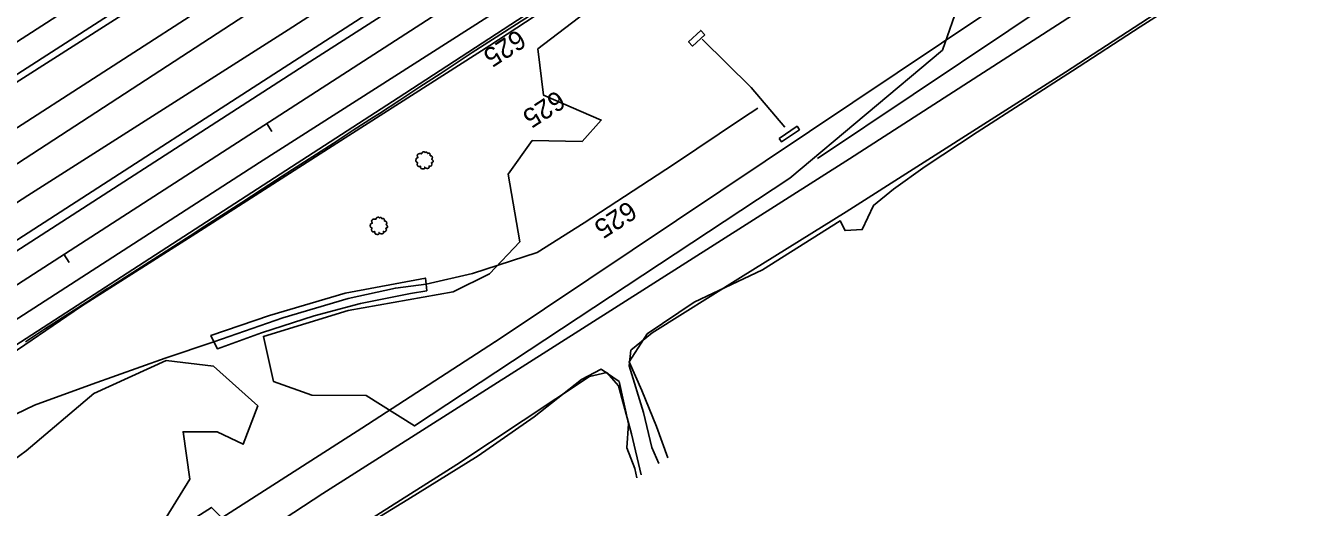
# Model space of a CAD drawing. Extents: x 1901471 to 1963503, y 756461 to 799997.
# Drawn here: x 1919489 to 1920021, y 766626 to 766826 of the extents above; entities that cross this region are included whole.
import ezdxf

# ---------------------------------------------------------------- set-up
doc = ezdxf.new("R2010")
doc.units = 0
for name, color, linetype in [('RD_DTM_BkLn1', 7, 'Continuous'), ('RD_EX_Bldg', 7, 'Continuous'), ('RD_EX_DR_ErosCtrl', 7, 'Continuous'), ('RD_EX_Fence_Other', 7, 'Continuous'), ('RD_EX_GuardRail', 7, 'Continuous'), ('RD_EX_H2O', 7, 'Continuous'), ('RD_EX_Road', 7, 'Continuous'), ('RD_EX_VEG', 7, 'Continuous'), ('RD_HC_Cl', 7, 'Continuous'), ('RD_HC_Data_Tic', 7, 'Continuous'), ('RD_HC_TX_Sta50', 7, 'Continuous')]:
    doc.layers.add(name, color=color, linetype=linetype)

# ---------------------------------------------------------------- blocks, each defined once
blk = doc.blocks.new('T2')
at = {"layer": 'RD_EX_VEG'}
for points in [[(0.05233333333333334, 7.213166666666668), (-0.24750000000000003, 7.238166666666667), (-0.5723333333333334, 7.138166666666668), (-0.8222500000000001, 7.038250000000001), (-1.0471666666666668, 6.963250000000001), (-1.2720833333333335, 6.863250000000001), (-1.5719166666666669, 6.688416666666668), (-1.7968333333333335, 6.488416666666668), (-1.9218333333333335, 6.2385833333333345), (-1.9718333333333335, 6.013666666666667), (-2.0217500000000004, 5.738833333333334), (-2.0217500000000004, 5.563833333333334), (-2.146666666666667, 5.538833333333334), (-2.296666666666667, 5.563833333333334), (-2.5465000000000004, 5.638833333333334), (-2.796416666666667, 5.638833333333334), (-3.0463333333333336, 5.638833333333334), (-3.3961666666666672, 5.613833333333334), (-3.7460000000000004, 5.613833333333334), (-4.020833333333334, 5.563833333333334), (-4.345750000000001, 5.513916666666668), (-4.720583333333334, 5.389000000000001), (-5.0704166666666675, 5.264000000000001), (-5.37025, 5.014083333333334), (-5.620166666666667, 4.539333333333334), (-5.745166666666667, 4.189500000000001), (-5.895083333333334, 3.9395833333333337), (-5.745166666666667, 3.489833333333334), (-5.570166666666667, 3.139916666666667), (-5.545250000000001, 2.9400000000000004), (-5.470250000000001, 2.5152500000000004), (-5.37025, 2.2903333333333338), (-5.245333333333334, 2.0903333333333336), (-5.320250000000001, 2.065416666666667), (-5.695166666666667, 2.015416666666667), (-5.995000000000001, 1.9155000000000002), (-6.419833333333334, 1.6905833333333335), (-6.644750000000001, 1.465666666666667), (-6.744750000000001, 1.1407500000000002), (-6.769666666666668, 0.7909166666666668), (-6.869583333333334, 0.5910833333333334), (-6.944583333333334, 0.3161666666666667), (-6.969583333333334, 0.2411666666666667), (-7.019583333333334, -0.08366666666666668), (-6.9195833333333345, -0.5335000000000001), (-6.894583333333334, -0.8833333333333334), (-6.769666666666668, -1.1082500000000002), (-6.619750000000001, -1.2830833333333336), (-6.444833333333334, -1.5330000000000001), (-6.045000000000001, -1.7579166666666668), (-5.7201666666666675, -1.8579166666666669), (-5.520250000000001, -1.8828333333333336), (-5.695166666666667, -2.382666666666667), (-5.745166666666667, -2.7325000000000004), (-5.870083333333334, -3.132333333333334), (-5.870083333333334, -3.2072500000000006), (-5.920000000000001, -3.682083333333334), (-5.770166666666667, -4.007000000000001), (-5.695166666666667, -4.38175), (-5.520250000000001, -4.606666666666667), (-5.245333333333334, -4.906583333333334), (-4.9205000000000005, -5.131416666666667), (-4.420666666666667, -5.256416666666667), (-4.020833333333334, -5.231416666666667), (-3.4460833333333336, -5.056500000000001), (-3.1962500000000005, -4.9815000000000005), (-3.2212500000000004, -5.156416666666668), (-3.1962500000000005, -5.531333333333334), (-3.1962500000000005, -5.956083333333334), (-3.0463333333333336, -6.280916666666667), (-2.946333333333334, -6.555833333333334), (-2.796416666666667, -6.805750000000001), (-2.4715000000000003, -7.030583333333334), (-2.07175, -7.1055833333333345), (-1.6469166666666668, -7.2555000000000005), (-1.1970833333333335, -7.330500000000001), (-0.6973333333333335, -7.355500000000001), (-0.09758333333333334, -7.205583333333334), (0.17725000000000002, -7.080583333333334), (0.27725000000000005, -6.905666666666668), (0.47716666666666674, -6.530833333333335), (0.4271666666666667, -6.3059166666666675), (0.4521666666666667, -5.706166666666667), (0.5520833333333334, -5.881166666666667), (0.7270833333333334, -6.231000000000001), (1.2268333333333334, -6.530833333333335), (1.626666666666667, -6.705750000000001), (2.101416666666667, -6.8557500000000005), (2.4013333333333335, -6.930666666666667), (2.8760833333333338, -6.8557500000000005), (3.2510000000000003, -6.780750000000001), (3.6257500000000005, -6.655750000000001), (3.9256666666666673, -6.380916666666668), (4.100583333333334, -6.106000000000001), (4.1505833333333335, -5.831166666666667), (4.2255, -5.456333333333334), (4.275500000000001, -5.281416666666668)], [(4.275500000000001, -5.281416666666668), (4.200583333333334, -5.106416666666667), (4.1505833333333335, -4.856583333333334), (4.2255, -4.881583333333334), (4.4004166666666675, -4.931583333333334), (4.675333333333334, -5.056500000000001), (4.900250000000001, -5.131416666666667), (5.225083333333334, -5.106416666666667), (5.500000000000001, -5.006500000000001), (5.949750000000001, -4.731583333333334), (6.224666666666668, -4.256833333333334), (6.499500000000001, -3.8570000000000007), (6.5745000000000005, -3.5321666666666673), (6.524500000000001, -3.3072500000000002), (6.499500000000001, -2.8075000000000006), (6.299583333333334, -2.5575833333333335), (6.249583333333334, -2.432666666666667), (6.1496666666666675, -2.0328333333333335), (6.224666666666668, -1.9828333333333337), (6.499500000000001, -1.9328333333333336), (6.874333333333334, -1.8079166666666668), (7.149250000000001, -1.6830000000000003), (7.374166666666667, -1.5080000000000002), (7.449083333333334, -1.2830833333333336), (7.424166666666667, -0.8833333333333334), (7.4740833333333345, -0.48350000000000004), (7.399166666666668, -0.3335), (7.299166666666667, -0.1836666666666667), (7.224166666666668, 0.016333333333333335), (7.074250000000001, 0.16616666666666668), (6.974333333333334, 0.3161666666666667), (6.874333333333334, 0.41608333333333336), (6.749416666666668, 0.5660833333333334), (6.5745000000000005, 0.6910000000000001), (6.424583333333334, 0.7410000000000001), (6.374583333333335, 0.8909166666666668), (6.524500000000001, 1.0908333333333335), (6.5745000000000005, 1.1907500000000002), (6.599416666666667, 1.4156666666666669), (6.824416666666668, 1.7655000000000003), (6.874333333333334, 2.1653333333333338), (6.824416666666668, 2.590166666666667), (6.774416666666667, 2.8650833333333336), (6.624416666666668, 3.139916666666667), (6.424583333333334, 3.3898333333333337), (6.299583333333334, 3.5647500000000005), (6.124666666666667, 3.689666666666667), (5.799833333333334, 3.814666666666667), (5.549916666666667, 3.864583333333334), (5.200083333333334, 3.864583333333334), (5.000166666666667, 3.9145833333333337), (5.025166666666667, 3.964583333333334), (5.025166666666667, 4.1145000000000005), (5.025166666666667, 4.389416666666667), (4.950166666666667, 4.839166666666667), (4.800250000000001, 5.339), (4.800250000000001, 5.364000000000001), (4.7002500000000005, 5.613833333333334), (4.475416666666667, 5.813750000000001), (4.3005, 5.913666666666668), (4.100583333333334, 6.038666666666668), (3.850666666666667, 6.063666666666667), (3.5508333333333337, 6.063666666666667), (3.2759166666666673, 6.013666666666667), (3.0760000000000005, 5.913666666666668), (2.9010833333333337, 5.788750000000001), (2.8260833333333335, 5.938666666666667), (2.726166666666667, 6.2385833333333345), (2.676166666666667, 6.3885000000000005), (2.52625, 6.563416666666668), (2.301416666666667, 6.7633333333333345), (1.8515000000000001, 6.888250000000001), (1.2268333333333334, 6.813333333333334), (0.9269166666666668, 6.613416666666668), (0.7770000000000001, 6.438500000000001), (0.7270833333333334, 6.563416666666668), (0.5270833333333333, 6.7633333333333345), (0.4271666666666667, 6.938250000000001), (0.25225000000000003, 7.063250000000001), (0.10233333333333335, 7.163166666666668), (0.0023333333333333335, 7.213166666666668)]]:
    blk.add_spline(points, degree=3, dxfattribs=at)

msp = doc.modelspace()

# ---------------------------------------------------------------- linework, layer by layer
at = {"layer": 'RD_DTM_BkLn1'}
msp.add_lwpolyline([(1919488.9696281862, 766694.8798975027), (1919497.353312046, 766700.3252241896), (1919505.736995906, 766705.7705508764), (1919514.120679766, 766711.215877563), (1919522.5043636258, 766716.6612042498), (1919523.4733127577, 766717.2905510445), (1919531.8984549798, 766722.6726785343), (1919540.3235972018, 766728.0548060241), (1919548.748739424, 766733.4369335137), (1919557.173881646, 766738.8190610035), (1919561.8048905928, 766741.7774301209), (1919570.2028041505, 766747.2044458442), (1919578.6007177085, 766752.631461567), (1919586.998631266, 766758.05847729), (1919595.396544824, 766763.4854930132), (1919599.6146566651, 766766.2113795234), (1919608.0086465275, 766771.6433790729), (1919616.4026363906, 766777.0753786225), (1919624.796626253, 766782.5073781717), (1919633.1906161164, 766787.9393777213), (1919635.6783761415, 766789.5492809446), (1919644.04459973, 766795.0253471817), (1919652.4108233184, 766800.5014134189), (1919660.7770469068, 766805.977479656), (1919669.1432704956, 766811.4535458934), (1919674.1136183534, 766814.706860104), (1919682.5215650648, 766820.1174888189), (1919690.9295117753, 766825.5281175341), (1919699.3374584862, 766830.938746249)], dxfattribs=at)
at = {"layer": 'RD_EX_Bldg'}
for points in [[(1919770.4300000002, 766822.1000000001), (1919765.3700000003, 766817.3900000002), (1919763.6600000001, 766819.2100000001), (1919768.7200000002, 766823.9300000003)], [(1919801.2700000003, 766779.1400000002), (1919808.6700000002, 766784.1900000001), (1919809.6300000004, 766782.7800000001), (1919802.2300000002, 766777.7300000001)]]:
    msp.add_lwpolyline(points, close=True, dxfattribs=at)
at = {"layer": 'RD_EX_DR_ErosCtrl'}
msp.add_lwpolyline([(1919655.3300000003, 766716.0200000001), (1919655.0000000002, 766718.7200000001), (1919654.6600000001, 766721.2400000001), (1919621.4000000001, 766715.05), (1919590.1100000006, 766705.81), (1919565.8600000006, 766697.4700000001), (1919567.0000000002, 766694.8900000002), (1919568.5400000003, 766691.9800000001), (1919586.7300000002, 766698.6200000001), (1919608.6200000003, 766705.6700000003), (1919627.8000000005, 766710.7400000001), (1919648.5300000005, 766714.8900000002)], close=True, dxfattribs=at)
at = {"layer": 'RD_EX_Fence_Other'}
for points in [[(1918791.4600000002, 766304.4500000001), (1918859.0200000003, 766347.7800000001), (1918926.5900000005, 766391.6000000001), (1918993.5000000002, 766434.6000000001), (1919060.0900000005, 766478.1000000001), (1919129.4500000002, 766521.2600000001), (1919208.4300000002, 766572.9200000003), (1919275.0200000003, 766616.2400000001), (1919288.5600000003, 766625.1400000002), (1919368.7200000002, 766677.07), (1919490.0100000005, 766755.55), (1919597.8000000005, 766824.1500000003), (1919718.6900000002, 766902.2300000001), (1919812.1700000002, 766963.3800000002), (1919906.8700000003, 767023.9200000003), (1919999.9500000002, 767084.8700000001), (1920092.4300000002, 767144.4100000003), (1920185.5200000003, 767204.55), (1920208.6900000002, 767220.3700000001), (1920218.1600000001, 767227.82), (1920227.8300000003, 767235.2700000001)], [(1919685.6000000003, 766696.2000000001), (1919959.9300000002, 766879.9600000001), (1920000.9700000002, 766909.56)], [(1919063.1600000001, 766300.4600000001), (1919133.7100000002, 766346.5000000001), (1919183.9100000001, 766378.8), (1919244.4700000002, 766418.1200000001), (1919295.0300000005, 766450.5400000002), (1919412.0300000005, 766527.9200000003), (1919566.0200000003, 766626.2100000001), (1919570.3500000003, 766621.8500000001), (1919628.3100000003, 766659.0300000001), (1919686.0200000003, 766696.4700000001)], [(1919683.5300000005, 766694.8600000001), (1919686.0200000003, 766696.4700000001)], [(1919683.5300000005, 766694.8600000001), (1919686.0200000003, 766696.4700000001)]]:
    msp.add_lwpolyline(points, dxfattribs=at)
at = {"layer": 'RD_EX_GuardRail'}
for points in [[(1919429.8700000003, 766653.5200000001), (1919512.2300000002, 766709.6300000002), (1919559.5500000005, 766739.7700000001), (1919617.9800000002, 766777.2500000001), (1919681.4300000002, 766817.6300000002), (1919743.6900000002, 766858.55), (1919797.1000000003, 766892.7200000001), (1919855.39, 766929.0100000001), (1919917.9200000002, 766969.9200000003), (1919949.2500000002, 766990.2800000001), (1920007.0200000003, 767027.4900000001), (1920017.9900000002, 767034.82)], [(1919817.1000000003, 766770.8400000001), (1919936.0000000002, 766850.56), (1919964.3600000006, 766869.3400000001)]]:
    msp.add_lwpolyline(points, dxfattribs=at)
at = {"layer": 'RD_EX_H2O'}
for points in [[(1919808.2400000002, 766978.32), (1919724.7500000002, 766922.57), (1919636.0400000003, 766866.8500000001), (1919456.3300000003, 766749.7000000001), (1919284.9400000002, 766640.5000000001)], [(1919769.2800000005, 766820.31), (1919789.6700000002, 766800.2700000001), (1919803.5900000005, 766783.8600000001)], [(1919472.9200000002, 766659.05), (1919492.7500000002, 766668.6000000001), (1919516.6000000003, 766677.2800000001), (1919546.8700000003, 766688.0200000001), (1919567.0000000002, 766694.8900000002), (1919595.5600000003, 766704.8600000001), (1919622.6600000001, 766712.81), (1919642.2400000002, 766717.1300000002), (1919655.0000000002, 766718.7200000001), (1919674.1900000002, 766723.1100000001), (1919700.9200000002, 766731.8500000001), (1919720.4100000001, 766744.1800000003), (1919757.4000000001, 766768.3500000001), (1919786.0400000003, 766787.4800000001), (1919792.4400000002, 766791.7300000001)]]:
    msp.add_lwpolyline(points, dxfattribs=at)
at = {"layer": 'RD_EX_Road'}
for points in [[(1918758.6600000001, 766335.3), (1918840.0900000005, 766388.2600000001), (1918915.4900000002, 766436.6400000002), (1919004.7600000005, 766494.6600000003), (1919093.2200000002, 766552.0300000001), (1919166.8200000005, 766599.6000000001), (1919238.4600000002, 766646.3500000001), (1919299.6600000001, 766686.1800000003), (1919363.1600000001, 766726.9100000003), (1919448.2000000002, 766781.7600000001), (1919521.4600000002, 766828.82), (1919605.2300000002, 766882.9500000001), (1919674.14, 766927.2800000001), (1919773.5100000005, 766991.3800000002), (1919868.89, 767052.9400000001), (1919967.1700000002, 767116.32), (1920061.1000000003, 767176.9800000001), (1920178.0600000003, 767252.32), (1920268.7300000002, 767310.8), (1920307.3600000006, 767335.8900000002)], [(1918763.0300000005, 766333.4800000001), (1918863.2000000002, 766399.08), (1918984.8600000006, 766477.8700000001), (1919117.7700000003, 766563.9900000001), (1919231.8600000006, 766638.1300000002), (1919299.5300000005, 766681.8600000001), (1919335.3000000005, 766704.8500000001), (1919462.9900000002, 766788.1700000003), (1919607.8100000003, 766880.6200000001), (1919741.8500000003, 766967.2700000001), (1919869.5400000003, 767049.4900000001), (1920027.3500000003, 767151.6100000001), (1920139.8400000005, 767224.1600000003), (1920266.14, 767305.56), (1920310.4500000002, 767334.2900000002)], [(1918753.2700000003, 766259.57), (1918827.5300000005, 766307.8), (1918893.6200000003, 766350.4700000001), (1918968.2000000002, 766398.3700000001), (1919055.0300000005, 766453.9400000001), (1919131.0800000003, 766503.6400000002), (1919173.5100000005, 766530.81), (1919222.3100000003, 766562.4700000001), (1919276.6500000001, 766597.6400000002), (1919300.1500000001, 766612.4900000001), (1919463.4300000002, 766718.4600000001), (1919608.7900000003, 766812.1200000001), (1919699.5500000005, 766870.4600000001), (1919804.64, 766938.5400000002), (1919890.6300000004, 766994.1500000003), (1919967.7400000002, 767044.1400000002), (1920041.1000000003, 767092.2500000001), (1920151.9900000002, 767163.3900000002), (1920248.2100000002, 767225.83), (1920367.9800000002, 767302.7800000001)], [(1918755.5600000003, 766266.2600000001), (1918829.9800000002, 766313.8400000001), (1918904.5600000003, 766362.3900000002), (1918967.2300000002, 766401.8800000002), (1919050.4600000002, 766455.2500000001), (1919150.9900000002, 766520.9400000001), (1919226.5500000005, 766569.32), (1919299.9900000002, 766616.82), (1919437.0100000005, 766705.81), (1919587.6300000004, 766802.9600000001), (1919674.6900000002, 766859.3400000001), (1919814.2600000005, 766949.0300000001), (1919953.0000000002, 767039.5400000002), (1920072.9500000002, 767117.3400000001), (1920217.5000000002, 767209.7900000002), (1920365.3600000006, 767304.4500000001)], [(1920341.3600000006, 767256.7100000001), (1920187.8200000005, 767157.7600000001), (1920049.2900000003, 767068.1900000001), (1919940.1000000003, 766997.3900000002), (1919863.3300000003, 766948.4300000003), (1919779.0500000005, 766894.1800000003), (1919712.5100000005, 766850.1600000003), (1919585.9300000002, 766769.1300000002), (1919449.1000000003, 766680.9200000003), (1919354.9300000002, 766619.6800000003), (1919300.1500000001, 766583.9300000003), (1919230.4700000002, 766539.05), (1919169.2700000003, 766499.4800000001), (1919111.8200000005, 766462.5900000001), (1919042.4600000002, 766417.7900000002), (1918955.9700000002, 766362.06), (1918868.1600000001, 766305.6800000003), (1918774.6500000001, 766245.05)], [(1920342.9800000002, 767247.3800000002), (1920159.1800000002, 767131.7100000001), (1920026.2500000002, 767043.6900000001), (1919811.7800000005, 766905.7700000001), (1919643.4600000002, 766795.9100000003), (1919402.7300000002, 766640.31), (1919299.9900000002, 766574.06), (1919256.4100000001, 766546.07), (1919183.14, 766498.82), (1919092.5600000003, 766440.1500000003), (1919017.8200000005, 766391.9300000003), (1918959.39, 766353.82), (1918876.3200000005, 766301.1900000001), (1918792.9300000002, 766247.0900000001)], [(1918306.6100000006, 765760.82), (1918309.8100000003, 765765.9400000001), (1918297.5300000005, 765780.07), (1918389.3500000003, 765839.0300000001), (1918486.39, 765902.2900000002), (1918618.4300000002, 765988.7300000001), (1918754.7800000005, 766076.4100000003), (1918895.4300000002, 766167.1500000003), (1919049.5900000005, 766266.8), (1919182.5500000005, 766353.55), (1919299.2500000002, 766428.6300000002), (1919473.4900000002, 766541.2300000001), (1919612.2300000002, 766632.0200000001), (1919830.2900000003, 766770.7600000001), (1919972.0800000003, 766862.1100000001), (1920034.2600000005, 766896.5100000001), (1920082.3500000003, 766919.1800000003), (1920134.3100000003, 766939.9100000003), (1920176.0400000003, 766954.55), (1920231.8700000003, 766969.8900000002), (1920265.5900000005, 766976.2500000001), (1920274.0800000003, 766977.8400000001)], [(1920228.8400000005, 766948.9800000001), (1920185.9900000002, 766937.56), (1920110.8200000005, 766910.4700000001), (1920046.7000000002, 766882.1400000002), (1919988.1100000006, 766851.1900000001), (1919919.8400000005, 766806.55), (1919828.9100000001, 766748.7900000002), (1919785.2400000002, 766721.57), (1919748.6200000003, 766698.55), (1919739.8000000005, 766691.3500000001), (1919739.0700000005, 766684.8900000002), (1919744.9500000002, 766665.5000000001), (1919748.4700000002, 766651.1100000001), (1919751.3600000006, 766644.3700000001)], [(1919744.0900000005, 766639.7200000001), (1919740.1000000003, 766656.6900000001), (1919734.6600000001, 766676.6600000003), (1919729.8200000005, 766682.1000000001), (1919722.6200000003, 766680.4800000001), (1919667.6900000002, 766644.06), (1919564.5800000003, 766578.7000000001), (1919497.2889596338, 766533.8374721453), (1919494.4030965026, 766530.8464334), (1919492.9514403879, 766522.3784393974), (1919495.9900000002, 766512.1600000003), (1919508.7600000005, 766487.5900000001)]]:
    msp.add_lwpolyline(points, dxfattribs=at)
at = {"layer": 'RD_EX_VEG'}
for points in [[(1919755.14, 766646.7800000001), (1919750.4600000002, 766659.7900000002), (1919744.2700000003, 766674.6600000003), (1919739.0400000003, 766686.56), (1919746.5300000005, 766698.1000000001), (1919766.0400000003, 766711.3), (1919794.3600000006, 766724.6900000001), (1919826.4800000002, 766745.0300000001), (1919828.5000000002, 766740.9300000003), (1919835.64, 766741.4000000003), (1919840.2800000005, 766751.4000000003), (1919848.6100000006, 766758.06), (1919861.7000000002, 766767.4600000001), (1919883.2300000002, 766781.7300000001), (1919922.7300000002, 766807.1300000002), (1919950.8100000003, 766825.3400000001), (1919990.3100000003, 766850.6200000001), (1920044.0800000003, 766878.1600000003)], [(1919875.8700000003, 766835.9000000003), (1919868.8500000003, 766815.7700000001), (1919805.6600000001, 766762.6300000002), (1919650.2000000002, 766660.0300000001), (1919630.1500000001, 766672.55), (1919607.6800000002, 766672.7800000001), (1919591.7700000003, 766678.4000000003), (1919587.5500000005, 766697.1200000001), (1919622.6600000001, 766707.8900000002), (1919666.1900000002, 766715.6100000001), (1919681.2900000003, 766723.08), (1919693.7300000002, 766736.2700000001), (1919689.0000000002, 766764.3700000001), (1919698.9500000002, 766778.3), (1919719.6000000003, 766777.81), (1919727.5000000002, 766786.7500000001), (1919703.6300000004, 766797.05), (1919701.2900000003, 766816.2400000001), (1919737.8000000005, 766844.32)], [(1919447.14, 766618.7200000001), (1919489.2600000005, 766649.6100000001), (1919517.3500000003, 766673.4800000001), (1919547.3000000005, 766687.06), (1919566.9600000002, 766684.7200000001), (1919585.2100000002, 766668.3400000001), (1919579.1300000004, 766652.4200000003), (1919568.3600000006, 766657.57), (1919554.3200000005, 766657.57), (1919557.1300000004, 766637.9100000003), (1919547.3000000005, 766622.0000000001), (1919524.3700000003, 766619.6600000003), (1919507.9800000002, 766602.3400000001), (1919495.3500000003, 766587.3600000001), (1919470.5400000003, 766583.1500000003)], [(1919511.3000000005, 766489.2700000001), (1919505.2600000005, 766504.2300000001), (1919498.9500000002, 766518.7500000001), (1919500.5000000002, 766531.4800000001), (1919531.1900000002, 766546.9400000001), (1919540.8300000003, 766557.9500000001), (1919560.4600000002, 766571.9900000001), (1919584.0200000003, 766588.1700000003), (1919619.5900000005, 766612.5000000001), (1919647.4300000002, 766629.4500000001), (1919676.5800000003, 766647.6500000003), (1919699.6600000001, 766663.7700000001), (1919719.2900000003, 766679.1800000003), (1919727.5000000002, 766683.4600000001), (1919734.8700000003, 766678.3500000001), (1919738.8000000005, 766660.8600000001), (1919738.0900000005, 766650.9800000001), (1919741.4200000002, 766642.3), (1919742.2500000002, 766638.55)]]:
    msp.add_lwpolyline(points, dxfattribs=at)
at = {"layer": 'RD_HC_Cl'}
for p, q in [((1926729.5176193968, 771495.9286460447), (1917217.2707724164, 765354.9153898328)), ((1926745.7566169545, 771470.7766377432), (1917232.2344163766, 765328.8252854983)), ((1925391.9794752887, 770532.94101177), (1917300.1886650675, 765307.3052403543))]:
    msp.add_line(p, q, dxfattribs=at)
at = {"layer": 'RD_HC_Data_Tic'}
for p, q in [((1919588.942861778, 766785.3706133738), (1919591.1128719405, 766782.0103967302)), ((1919504.9374456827, 766731.1203593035), (1919507.1074558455, 766727.7601426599))]:
    msp.add_line(p, q, dxfattribs=at)

# ---------------------------------------------------------------- block references
at = {"layer": 'RD_EX_VEG', "xscale": 0.4921259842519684, "yscale": 0.4921259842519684}
for p in [(1919654.1800000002, 766770.1000000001), (1919635.2700000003, 766742.9800000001)]:
    msp.add_blockref('T2', p, dxfattribs=at)

# ---------------------------------------------------------------- texts
at = {"layer": 'RD_HC_TX_Sta50'}
for rotation, p in [(212.8458901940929, (1919692.9226485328, 766824.6207995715)), (212.84637793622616, (1919709.2014118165, 766799.4088909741)), (212.85416067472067, (1919738.8455468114, 766753.6138365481))]:
    msp.add_text('625', height=8.000000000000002, rotation=rotation, dxfattribs=at).set_placement(p)

doc.saveas('drawing.dxf')
